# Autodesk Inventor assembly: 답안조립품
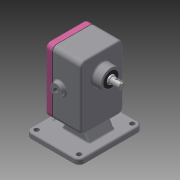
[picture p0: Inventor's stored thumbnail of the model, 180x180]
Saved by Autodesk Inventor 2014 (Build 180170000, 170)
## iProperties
Created: 2020-04
Part Number: 답안조립품
Document SubType Name: Assembly
Designer: kh
Author: kh
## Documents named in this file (11)
- C:\Users\kh\Desktop\이주현 700407V1027\답안조립품.iam
- C:\Users\kh\Desktop\이주현 700407V1027\본체 700407V1027.ipt
- C:\Users\kh\Desktop\이주현 700407V1027\개스킷.ipt
- C:\Users\kh\Desktop\이주현 700407V1027\메인축.ipt
- C:\Users\kh\Desktop\이주현 700407V1027\베어링부시.ipt
- C:\Users\kh\Desktop\이주현 700407V1027\볼트 M5.ipt
- C:\Users\kh\Desktop\이주현 700407V1027\서브축.ipt
- C:\Users\kh\Desktop\이주현 700407V1027\스퍼기어.ipt
- C:\Users\kh\Desktop\이주현 700407V1027\오일 실 16 28 7.ipt
- C:\Users\kh\Desktop\이주현 700407V1027\커버.ipt
- C:\Users\kh\Desktop\이주현 700407V1027\키 6 x 6 x 18.ipt
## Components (1 placed, 1 different names)
1. 개스킷:1 — 플러쉬:2
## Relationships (1: Flush 1)
- 플러쉬:2 [Flush]: 개스킷:1
